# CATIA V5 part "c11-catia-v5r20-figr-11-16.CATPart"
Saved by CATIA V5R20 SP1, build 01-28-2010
Part number: Part1
Bounding box of the stored display mesh (mm): x -112.891 to 155.069, y -166 to 177, z -20.381 to 17.354
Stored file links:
  D:\v5_r20\psrt_files_downloaded\c11\c11-catia-v5r20-figr-11-16.CATPart
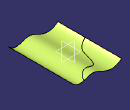
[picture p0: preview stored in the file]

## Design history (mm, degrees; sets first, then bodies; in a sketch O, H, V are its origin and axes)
Set1
  Sketch1 on zx-plane, origin (0, 0, 0), H (-1, 0, 0), V (0, 0, 1)
    spline S1 through (-155.0686, 17.3535) (-88.0787, 0) (-53.6625, 10.5338) (-6.5258, 0) (112.8909, 0)
    point P1 (-88.0787, 0)
    point P2 (-6.5258, 0)
    point P3 (112.8909, 0)
    coincidence: P1 H, P2 H, P3 H
  Extrude1: Element1 Sketch1, Lim1 177, Lim2 166, Direction zx-plane
  Sketch2 on xy-plane, origin (0, 0, 0), H (1, 0, 0), V (0, 1, 0)
    spline S1 through (-167.4699, -22.0252) (-66.0833, 12.4475) (-43.2893, 80.3989) (-11.0164, 123.7609) (37.393, 134.2276) (93.5198, 192.542)
  Extrude2: Element1 Sketch2, Lim1 94, Lim2 109, Direction xy-plane
  Trim1: Element1 Extrude1, Element2 Extrude2
  DatumSurface1
  DatumSurface2
  StUntrimFeature1 "CATStUntrimFeatureName": SpecToUntrim DatumSurface1
Body1 (main body)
